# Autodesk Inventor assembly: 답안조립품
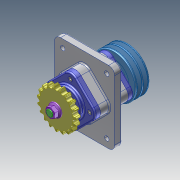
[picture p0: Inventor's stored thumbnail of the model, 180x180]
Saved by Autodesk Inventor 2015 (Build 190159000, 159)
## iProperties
Created: 2026-07
Part Number: 답안조립품
Document SubType Name: Assembly
Designer: USER
Author: USER
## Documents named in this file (12)
- C:\Users\USER\Desktop\760705V1013\답안조립품.iam
- C:\Users\USER\Desktop\760705V1013\본체.ipt
- C:\Users\USER\Desktop\760705V1013\가져온 구성요소\6각 구멍붙이 볼트 M6x16\6각 구멍붙이 볼트 M6x16.ipt
- C:\Users\USER\Desktop\760705V1013\가져온 구성요소\6각 플랜지 너트 M16\6각 플랜지 너트 M16.ipt
- C:\Users\USER\Desktop\760705V1013\가져온 구성요소\V-벨트풀리\V-벨트풀리.ipt
- C:\Users\USER\Desktop\760705V1013\가져온 구성요소\깊은 홈 볼 베어링 6206\깊은 홈 볼 베어링 6206.ipt
- C:\Users\USER\Desktop\760705V1013\가져온 구성요소\오일 실 30 45 8\오일 실 30 45 8.ipt
- C:\Users\USER\Desktop\760705V1013\가져온 구성요소\체인 스프로킷\체인 스프로킷.ipt
- C:\Users\USER\Desktop\760705V1013\가져온 구성요소\축\축.ipt
- C:\Users\USER\Desktop\760705V1013\가져온 구성요소\칼라\칼라.ipt
- C:\Users\USER\Desktop\760705V1013\가져온 구성요소\커버\커버.ipt
- C:\Users\USER\Desktop\760705V1013\가져온 구성요소\평행 키 6x6x20\평행 키 6x6x20.ipt
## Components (11 placed, 3 different names)
1. 6각 구멍붙이 볼트 M6x16:1
2. 6각 플랜지 너트 M16:1
3. V-벨트풀리:1
4. 6각 플랜지 너트 M16:2
5. 6각 구멍붙이 볼트 M6x16:2
6. 6각 구멍붙이 볼트 M6x16:3
7. 6각 구멍붙이 볼트 M6x16:4
8. 6각 구멍붙이 볼트 M6x16:5
9. 6각 구멍붙이 볼트 M6x16:6
10. 6각 구멍붙이 볼트 M6x16:7
11. 6각 구멍붙이 볼트 M6x16:8
